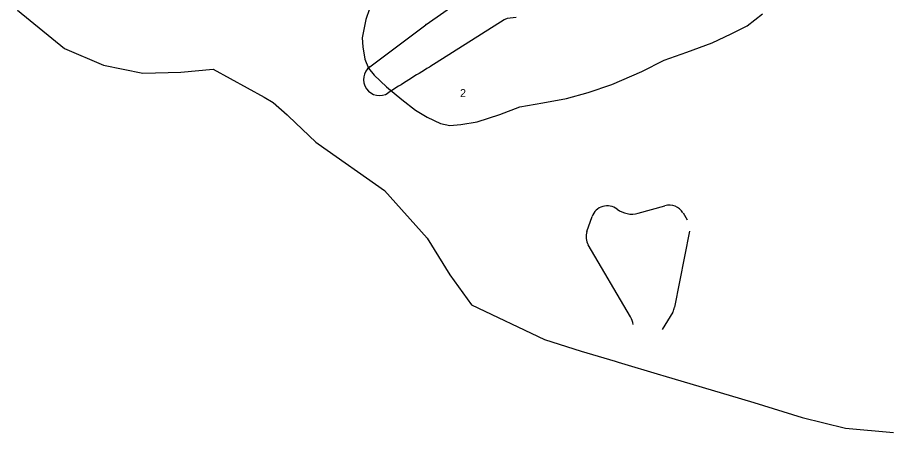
# Model space of a CAD drawing. Extents: x -445049 to -430649, y -1142304 to -1129816.
# Drawn here: x -444771 to -443678, y -1134562 to -1134043 of the extents above; entities that cross this region are included whole.
import ezdxf

# ---------------------------------------------------------------- set-up
doc = ezdxf.new("R2010")
doc.units = 0
for name, color, linetype in [('Vrstva 23', 7, 'Continuous'), ('Vrstva 51', 7, 'Continuous'), ('Vrstva 7', 7, 'Continuous')]:
    doc.layers.add(name, color=color, linetype=linetype)

msp = doc.modelspace()

# ---------------------------------------------------------------- linework, layer by layer
at = {"layer": 'Vrstva 23'}
for p, q in [((-444260.8, -1134051.9), (-444153.9, -1133977.1)), ((-444163.4, -1134046.2), (-444256.1, -1134104.9)), ((-444148.3, -1134043.2), (-444159.5, -1134044.5)), ((-444331.2, -1134104.8), (-444261.4, -1134052.3)), ((-443995.8, -1134287.9), (-443962.5, -1134278.5)), ((-443939.9, -1134287.4), (-443934.6, -1134296.2)), ((-444059.9, -1134310.8), (-444053.4, -1134292)), ((-443931.7, -1134310.2), (-443950.4, -1134405.2)), ((-444005.6, -1134417.5), (-444058.3, -1134327.5)), ((-443952.8, -1134411.5), (-443965.8, -1134433.4))]:
    msp.add_line(p, q, dxfattribs=at)
for centre, radius, start, end in [((-444149.2, -1134072.6), 30, 110.2198, 118.3089), ((-444249.4, -1134068.2), 20, 124.9539, 126.9629), ((-444319.1, -1134120.7), 20, 126.9629, 303.1119), ((-444266.8, -1134088), 20, 300.9133, 302.3401), ((-443441, -1135467.1), 1587.4, 120.9133, 123.1119), ((-444034.5, -1134298.6), 20, 52.3247, 160.864), ((-443957.1, -1134297.8), 20, 31.1463, 105.7015), ((-444003.9, -1134259), 30, 232.3247, 285.7015), ((-444041, -1134317.4), 20, 160.864, 210.3258), ((-443970, -1134401.3), 20, 329.2942, 348.8542), ((-444031.5, -1134432.6), 30, 10.3353, 30.3258)]:
    msp.add_arc(centre, radius, start, end, dxfattribs=at)
at = {"layer": 'Vrstva 51'}
msp.add_lwpolyline([(-444331.5, -1134032.2), (-444336.1, -1134045.8), (-444340.9, -1134068.5), (-444339.7, -1134080), (-444337.2, -1134095.1), (-444333, -1134106.7), (-444325.9, -1134115.5), (-444310.5, -1134130), (-444291.1, -1134145.9), (-444274.1, -1134159), (-444259.4, -1134167.8), (-444243, -1134175.7), (-444231.3, -1134178.1), (-444217.4, -1134177.1), (-444197, -1134173.5), (-444168.6, -1134164.3), (-444143.7, -1134154.9), (-444115, -1134149.8), (-444085.3, -1134144.4), (-444058.5, -1134137.1), (-444028.9, -1134127), (-443991.2, -1134110.8), (-443963.3, -1134096.4), (-443935.3, -1134086.7), (-443903.6, -1134074.7), (-443879.6, -1134063.6), (-443859.8, -1134053.8), (-443840.7, -1134038.8)], dxfattribs=at)
at = {"layer": 'Vrstva 7'}
msp.add_lwpolyline([(-444771.3, -1134034.1), (-444712.6, -1134082), (-444663.9, -1134102.8), (-444614.6, -1134112.6), (-444567.3, -1134111.4), (-444527, -1134107.9), (-444463.1, -1134142.8), (-444451.8, -1134149.6), (-444434.4, -1134165), (-444432.7, -1134166.6), (-444398.8, -1134198.9), (-444395.6, -1134201.1), (-444312.8, -1134259.7), (-444259.6, -1134319), (-444231.2, -1134365.1), (-444204.2, -1134402.6), (-444112.9, -1134445.6), (-444067.3, -1134460.2), (-444024.8, -1134472.9), (-444020.9, -1134474), (-443968, -1134489.8), (-443965.3, -1134490.6), (-443866.9, -1134520), (-443851.3, -1134524.7), (-443791, -1134543.3), (-443737, -1134556.5), (-443676.9, -1134562.1)], dxfattribs=at)
msp.add_lwpolyline([(-444771.3, -1134034.1), (-444712.6, -1134082), (-444663.9, -1134102.8), (-444614.6, -1134112.6), (-444567.3, -1134111.4), (-444527, -1134107.9), (-444463.1, -1134142.8), (-444451.8, -1134149.6), (-444434.4, -1134165), (-444432.7, -1134166.6), (-444398.8, -1134198.9), (-444395.6, -1134201.1), (-444312.8, -1134259.7), (-444259.6, -1134319), (-444231.2, -1134365.1), (-444204.2, -1134402.6), (-444112.9, -1134445.6), (-444067.3, -1134460.2), (-444024.8, -1134472.9), (-444020.9, -1134474), (-443968, -1134489.8), (-443965.3, -1134490.6), (-443866.9, -1134520), (-443851.3, -1134524.7), (-443791, -1134543.3), (-443737, -1134556.5), (-443676.9, -1134562.1)], dxfattribs=at)
msp.add_lwpolyline([(-444771.3, -1134034.1), (-444712.6, -1134082), (-444663.9, -1134102.8), (-444614.6, -1134112.6), (-444567.3, -1134111.4), (-444527, -1134107.9), (-444463.1, -1134142.8), (-444451.8, -1134149.6), (-444434.4, -1134165), (-444432.7, -1134166.6), (-444398.8, -1134198.9), (-444395.6, -1134201.1), (-444312.8, -1134259.7), (-444259.6, -1134319), (-444231.2, -1134365.1), (-444204.2, -1134402.6), (-444112.9, -1134445.6), (-444067.3, -1134460.2), (-444024.8, -1134472.9), (-444020.9, -1134474), (-443968, -1134489.8), (-443965.3, -1134490.6), (-443866.9, -1134520), (-443851.3, -1134524.7), (-443791, -1134543.3), (-443737, -1134556.5), (-443676.9, -1134562.1)], dxfattribs=at)

# ---------------------------------------------------------------- texts
at = {"layer": 'Vrstva 51'}
msp.add_text('2', height=10, dxfattribs=at).set_placement((-444218.5, -1134142.7))

doc.saveas('drawing.dxf')
